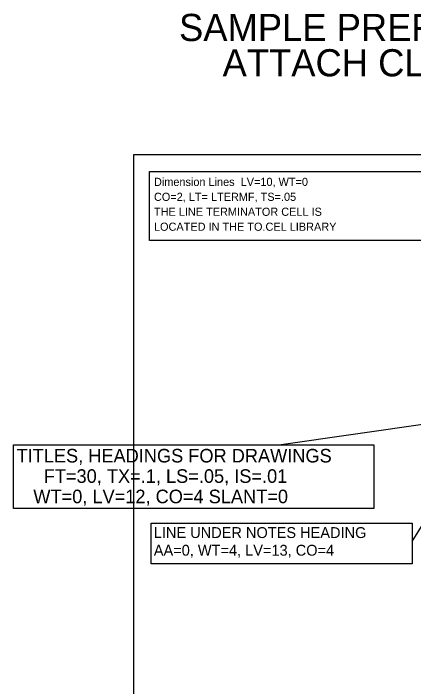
# Model space of a CAD drawing. Extents: x -0.5 to 21.6, y 4.3 to 17.8.
# Drawn here: x -0.49 to 2.452, y 12.375 to 17.329 of the extents above; entities that cross this region are included whole.
import ezdxf

# ---------------------------------------------------------------- set-up
doc = ezdxf.new("R2010")
doc.units = 0
for name, color, linetype in [('DETL-DIMS', 7, 'Continuous'), ('DETL-LINE', 7, 'Continuous'), ('DETL-TITL', 7, 'Continuous'), ('TTLB-TEXT', 7, 'Continuous'), ('USER-BORD', 7, 'Continuous')]:
    doc.layers.add(name, color=color, linetype=linetype)

msp = doc.modelspace()

# ---------------------------------------------------------------- linework, layer by layer
at = {"layer": 'DETL-DIMS'}
for p, q in [((1.4601, 14.1527), (2.7134, 14.3344)), ((2.4408, 13.4428), (2.9424, 14.2526))]:
    msp.add_line(p, q, dxfattribs=at)
msp.add_lwpolyline([(0.509, 16.1657), (2.5807, 16.1657), (2.5807, 15.6587), (0.509, 15.6587)], close=True, dxfattribs=at)
at = {"layer": 'DETL-LINE'}
msp.add_lwpolyline([(0.3943, 14.1527), (0.3943, 16.2906), (7.7685, 16.2906), (7.7685, 5.9375), (0.3943, 5.9375), (0.3943, 13.6862)], dxfattribs=at)
at = {"layer": 'DETL-TITL'}
for points in [[(-0.4905, 14.1527), (2.1606, 14.1527), (2.1606, 13.6862), (-0.4905, 13.6862)], [(0.5217, 13.5766), (2.4408, 13.5766), (2.4408, 13.2767), (0.5217, 13.2767)]]:
    msp.add_lwpolyline(points, close=True, dxfattribs=at)
at = {"layer": 'TTLB-TEXT'}
for p, q in [((0.3943, 7.3883), (0.3943, 16.2906)), ((0.3943, 16.2906), (7.7685, 16.2906))]:
    msp.add_line(p, q, dxfattribs=at)
msp.add_lwpolyline([(0.3943, 16.2906), (7.7685, 16.2906), (7.7685, 5.9375), (0.3943, 5.9375)], close=True, dxfattribs=at)
at = {"layer": 'USER-BORD'}
for p, q in [((0.3943, 16.2906), (7.7685, 16.2906)), ((0.3943, 14.1527), (0.3943, 16.2906)), ((0.3943, 7.3883), (0.3943, 13.6862))]:
    msp.add_line(p, q, dxfattribs=at)

# ---------------------------------------------------------------- texts
at = {"layer": 'DETL-DIMS'}
for s, p in [('Dimension Lines  LV=10, WT=0', (0.5427, 16.0594)), ('CO=2, LT= LTERMF, TS=.05  ', (0.5427, 15.9494)), ('THE LINE TERMINATOR CELL IS', (0.5427, 15.8394)), ('LOCATED IN THE TO.CEL LIBRARY', (0.5427, 15.7294))]:
    msp.add_text(s, height=0.06, dxfattribs=at).set_placement(p)
at = {"layer": 'DETL-LINE'}
for s, p in [('SAMPLE PREFERENCE TABLE FOR STANDARDS', (0.727, 17.126)), ('ATTACH CLORMDSHA.CTB COLOR TABLE', (1.0473, 16.866))]:
    msp.add_text(s, height=0.2, dxfattribs=at).set_placement(p)
at = {"layer": 'DETL-TITL'}
for s, height, p in [('TITLES, HEADINGS FOR DRAWINGS', 0.1, (-0.4681, 14.0238)), ('FT=30, TX=.1, LS=.05, IS=.01', 0.1, (-0.2681, 13.8738)), ('WT=0, LV=12, CO=4 SLANT=0', 0.1, (-0.3445, 13.7238)), ('LINE UNDER NOTES HEADING ', 0.08, (0.5416, 13.4678)), ('AA=0, WT=4, LV=13, CO=4', 0.08, (0.5416, 13.3378))]:
    msp.add_text(s, height=height, dxfattribs=at).set_placement(p)

doc.saveas('drawing.dxf')
